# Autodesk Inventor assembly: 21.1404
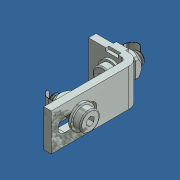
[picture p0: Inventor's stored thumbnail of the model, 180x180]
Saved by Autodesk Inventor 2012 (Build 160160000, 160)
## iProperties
Created: 2007-01
Part Number: 21.1404
Document SubType Name: Assembly
Designer: Andy Moles
Description: GUARD UNIT FIXING ANGLE 45
Author: Andy Moles
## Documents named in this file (5)
- C:\Andys Backup Data\ANDY'S INVENTOR\INVENTOR LIBRARIES\PARTS LIBRARY\FASTENING ELEMENTS\21.1404 GUARD UNIT FIXING ANGLE 45.iam
- C:\Andys Backup Data\ANDY'S INVENTOR\INVENTOR LIBRARIES\PARTS LIBRARY\FASTENING ELEMENTS\SUBCOMPONENTS\21.1404 GUARD UNIT FIXING ANGLE 45.ipt
- C:\Andys Backup Data\ANDY'S INVENTOR\INVENTOR LIBRARIES\PARTS LIBRARY\FASTENING ELEMENTS\SCREWS CAP\21.1202 M8X20.ipt
- C:\Andys Backup Data\ANDY'S INVENTOR\INVENTOR LIBRARIES\PARTS LIBRARY\FASTENING ELEMENTS\NUTS\21.1351_2 M8 SQUARE NUT POS FXG.ipt
- C:\Andys Backup Data\ANDY'S INVENTOR\INVENTOR LIBRARIES\PARTS LIBRARY\FASTENING ELEMENTS\WASHERS\21.1127 M8 ROUND WASHER.ipt
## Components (7 placed, 4 different names)
1. 21.1404 GUARD UNIT FIXING ANGLE 45:1 — Insert:3, Mate:5, Mate:6, Mate:7, Mate:8, Flush:1, Mate:9, Mate:10, Angle:1
2. 21.1202  M8 x 20:1 — Insert:1, Mate:3, Mate:10
3. 21.1127 WASHER M8:1 — Insert:1, Mate:6
4. 21.1127 WASHER M8:2 — Insert:2, Insert:3
5. 21.1202  M8 x 20:2 — Insert:2, Mate:4
6. 21.1351_2 M8 SQUARE NUT POS FXG:1 — Mate:4, Mate:5
7. 21.1351_2 M8 SQUARE NUT POS FXG:2 — Mate:3, Mate:7, Angle:1
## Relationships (13: Mate 8, Insert 3, Flush 1, Angle 1)
- Insert:1: 21.1202  M8 x 20:1 ↔ 21.1127 WASHER M8:1
- Insert:2: 21.1127 WASHER M8:2 ↔ 21.1202  M8 x 20:2
- Mate:3: 21.1202  M8 x 20:1 ↔ 21.1351_2 M8 SQUARE NUT POS FXG:2
- Mate:4: 21.1202  M8 x 20:2 ↔ 21.1351_2 M8 SQUARE NUT POS FXG:1
- Insert:3: 21.1404 GUARD UNIT FIXING ANGLE 45:1 ↔ 21.1127 WASHER M8:2
- Mate:5: 21.1404 GUARD UNIT FIXING ANGLE 45:1 ↔ 21.1351_2 M8 SQUARE NUT POS FXG:1
- Mate:6: 21.1404 GUARD UNIT FIXING ANGLE 45:1 ↔ 21.1127 WASHER M8:1
- Mate:7: 21.1404 GUARD UNIT FIXING ANGLE 45:1 ↔ 21.1351_2 M8 SQUARE NUT POS FXG:2
- Mate:8: 21.1404 GUARD UNIT FIXING ANGLE 45:1
- Flush:1: 21.1404 GUARD UNIT FIXING ANGLE 45:1
- Mate:9: 21.1404 GUARD UNIT FIXING ANGLE 45:1
- Mate:10: 21.1404 GUARD UNIT FIXING ANGLE 45:1 ↔ 21.1202  M8 x 20:1
- Angle:1: 21.1404 GUARD UNIT FIXING ANGLE 45:1 ↔ 21.1351_2 M8 SQUARE NUT POS FXG:2
